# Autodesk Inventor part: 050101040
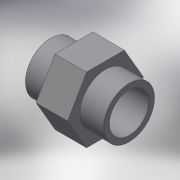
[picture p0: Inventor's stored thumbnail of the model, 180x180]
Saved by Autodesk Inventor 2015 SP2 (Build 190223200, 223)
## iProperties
Created: 2017-10
Part Number: 050101040
Material: Generic
Description: PLASSON THREADED SOCKET PVC 4"
Document SubType Name: Modeling
Designer: KIM
Density: 1 g/cm^3
Appearance: Default
Author: KIM
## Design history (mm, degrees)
derived "050101.ipt"
feature "Solid1::050101.ipt"
tag "TaggingFeature1"
body "Solid1"
other parameters: "d0" = 106, "d1" = 110.072, "d3" = 110.072, "d4" = 99.0648, "d7" = 126.5828, "d8" = 126.5828, "d10" = 28, "d13" = 0, "d14" = 1.10072, "d15" = 28, "G_" = 110.072, "B_" = 28, "H_" = 106
